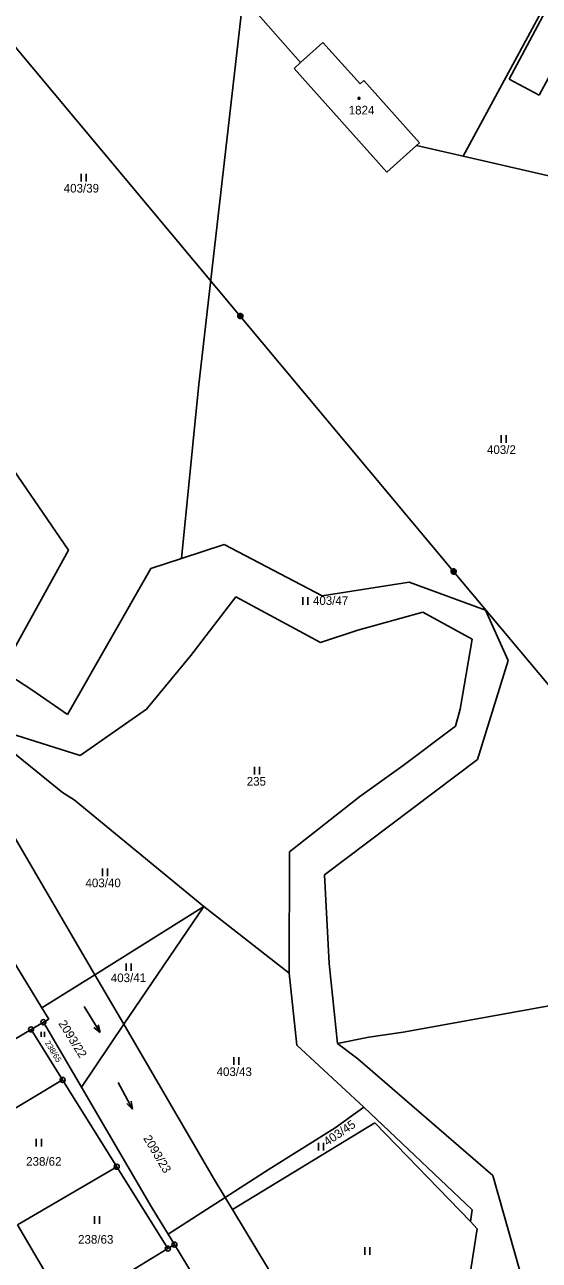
# Model space of a CAD drawing. Extents: x -795483 to -789093, y -1112258 to -1108741.
# Drawn here: x -791523.5 to -791422.1, y -1111209.4 to -1110965.8 of the extents above; entities that cross this region are included whole.
import ezdxf

# ---------------------------------------------------------------- set-up
doc = ezdxf.new("R2010")
doc.units = 0
for name, color, linetype in [('Vrstva 1', 7, 'Continuous'), ('Vrstva 12', 7, 'Continuous'), ('Vrstva 14', 7, 'Continuous'), ('Vrstva 15', 7, 'Continuous'), ('Vrstva 23', 7, 'Continuous'), ('Vrstva 25', 7, 'Continuous'), ('Vrstva 26', 7, 'Continuous'), ('Vrstva 28', 7, 'Continuous')]:
    doc.layers.add(name, color=color, linetype=linetype)

msp = doc.modelspace()

# ---------------------------------------------------------------- linework, layer by layer
at = {"layer": 'Vrstva 1'}
for p, q in [((-791417.2, -1110954.85), (-791437.16, -1110991.77)), ((-791428.08, -1110976.56), (-791416.64, -1110955.13)), ((-791410.64, -1110958.18), (-791422.14, -1110979.73)), ((-791480.51, -1110960.44), (-791489.29, -1111037.36)), ((-791480.51, -1110960.44), (-791469.18, -1110973.32)), ((-791464.78, -1110969.38), (-791469.18, -1110973.32)), ((-791464.78, -1110969.38), (-791457.46, -1110977.53)), ((-791470.46, -1110974.46), (-791469.18, -1110973.32)), ((-791470.46, -1110974.46), (-791452.15, -1110994.9)), ((-791457.46, -1110977.53), (-791456.71, -1110976.85)), ((-791456.71, -1110976.85), (-791445.73, -1110989.14)), ((-791422.14, -1110979.73), (-791428.08, -1110976.56)), ((-791445.73, -1110989.14), (-791446.31, -1110989.66)), ((-791452.15, -1110994.9), (-791446.31, -1110989.66)), ((-791446.31, -1110989.66), (-791437.16, -1110991.77)), ((-791437.16, -1110991.77), (-791391.97, -1111002.17)), ((-791566.04, -1110994.83), (-791514.9, -1111069.43)), ((-791489.29, -1111037.36), (-791492.66, -1111071.07)), ((-791514.9, -1111069.43), (-791528, -1111093.12)), ((-791484.25, -1111068.33), (-791492.66, -1111071.07)), ((-791484.25, -1111068.33), (-791464.93, -1111078.43)), ((-791498.67, -1111073.03), (-791492.66, -1111071.07)), ((-791515.12, -1111101.83), (-791498.67, -1111073.03)), ((-791464.93, -1111078.43), (-791447.81, -1111075.74)), ((-791447.81, -1111075.74), (-791432.71, -1111081.24)), ((-791481.94, -1111078.64), (-791490.78, -1111090.21)), ((-791481.94, -1111078.64), (-791465.25, -1111087.59)), ((-791457.92, -1111085.22), (-791445.08, -1111081.65)), ((-791445.08, -1111081.65), (-791435.37, -1111086.98)), ((-791432.71, -1111081.24), (-791428.25, -1111091.18)), ((-791465.25, -1111087.59), (-791457.92, -1111085.22)), ((-791437.72, -1111100.79), (-791435.37, -1111086.98)), ((-791499.56, -1111100.76), (-791490.78, -1111090.21)), ((-791428.25, -1111091.18), (-791434.3, -1111110.69)), ((-791528, -1111093.12), (-791522.13, -1111096.97)), ((-791522.13, -1111096.97), (-791515.12, -1111101.83)), ((-791512.58, -1111109.89), (-791499.56, -1111100.76)), ((-791438.63, -1111104.12), (-791437.72, -1111100.79)), ((-791533.06, -1111103.46), (-791512.58, -1111109.89)), ((-791533.06, -1111103.46), (-791516.11, -1111117.17)), ((-791448.93, -1111111.87), (-791438.63, -1111104.12)), ((-791552.06, -1111107.33), (-791520.15, -1111159.65)), ((-791536.7, -1111106.9), (-791509.72, -1111153.12)), ((-791434.3, -1111110.69), (-791464.44, -1111133.44)), ((-791457.52, -1111117.98), (-791448.93, -1111111.87)), ((-791516.11, -1111117.17), (-791513.78, -1111118.66)), ((-791471.33, -1111128.87), (-791457.52, -1111117.98)), ((-791488.21, -1111139.64), (-791513.78, -1111118.66)), ((-791471.33, -1111128.87), (-791471.4, -1111152.79)), ((-791464.44, -1111133.44), (-791463.52, -1111150.89)), ((-791509.72, -1111153.12), (-791488.21, -1111139.64)), ((-791488.21, -1111139.64), (-791504.02, -1111162.88)), ((-791488.21, -1111139.64), (-791471.4, -1111152.79)), ((-791463.52, -1111150.89), (-791461.89, -1111166.67)), ((-791520.15, -1111159.65), (-791509.72, -1111153.12)), ((-791509.72, -1111153.12), (-791504.02, -1111162.88)), ((-791471.4, -1111152.79), (-791469.91, -1111166.98)), ((-791448.95, -1111164.42), (-791401.41, -1111155.85)), ((-791520.15, -1111159.65), (-791518.81, -1111161.84)), ((-791518.81, -1111161.84), (-791519.85, -1111162.45)), ((-791541.09, -1111174.99), (-791522.29, -1111163.89)), ((-791522.29, -1111163.89), (-791519.85, -1111162.45)), ((-791516.08, -1111173.84), (-791522.29, -1111163.89)), ((-791513.94, -1111172.57), (-791519.85, -1111162.45)), ((-791504.02, -1111162.88), (-791512.35, -1111175.29)), ((-791486.32, -1111193.2), (-791504.02, -1111162.88)), ((-791455.73, -1111165.42), (-791448.95, -1111164.42)), ((-791456.74, -1111179.18), (-791469.91, -1111166.98)), ((-791461.89, -1111166.67), (-791455.73, -1111165.42)), ((-791461.89, -1111166.67), (-791457.92, -1111169.65)), ((-791457.92, -1111169.65), (-791431.26, -1111192.71)), ((-791535.12, -1111185.14), (-791516.08, -1111173.84)), ((-791505.4, -1111190.96), (-791516.08, -1111173.84)), ((-791513.94, -1111172.57), (-791512.35, -1111175.29)), ((-791512.35, -1111175.29), (-791498.42, -1111199.12)), ((-791456.74, -1111179.18), (-791462.36, -1111183.28)), ((-791435.39, -1111199.44), (-791456.74, -1111179.18)), ((-791482.6, -1111199.35), (-791454.56, -1111182.29)), ((-791462.36, -1111183.28), (-791475.38, -1111191.43)), ((-791454.56, -1111182.29), (-791435.71, -1111201.77)), ((-791524.94, -1111202.42), (-791505.4, -1111190.96)), ((-791505.4, -1111190.96), (-791495.34, -1111207.09)), ((-791486.32, -1111193.2), (-791484.03, -1111196.99)), ((-791475.38, -1111191.43), (-791484.03, -1111196.99)), ((-791422.96, -1111222.17), (-791431.26, -1111192.71)), ((-791484.03, -1111196.99), (-791495.3, -1111204.25)), ((-791484.03, -1111196.99), (-791482.6, -1111199.35)), ((-791495.3, -1111204.25), (-791498.42, -1111199.12)), ((-791482.6, -1111199.35), (-791460.81, -1111235.4)), ((-791435.39, -1111199.44), (-791435.71, -1111201.77)), ((-791524.94, -1111202.42), (-791515.11, -1111219.12)), ((-791434.35, -1111203.18), (-791436.4, -1111216.11)), ((-791435.71, -1111201.77), (-791434.35, -1111203.18)), ((-791494.05, -1111206.31), (-791495.3, -1111204.25)), ((-791495.34, -1111207.09), (-791515.11, -1111219.12)), ((-791495.34, -1111207.09), (-791494.05, -1111206.31)), ((-791483.17, -1111224.05), (-791494.05, -1111206.31))]:
    msp.add_line(p, q, dxfattribs=at)
at = {"layer": 'Vrstva 12'}
for p, q in [((-791526.73, -1110968.63), (-791481.05, -1111023.27)), ((-791481.05, -1111023.27), (-791439.03, -1111073.62)), ((-791439.03, -1111073.62), (-791390.3, -1111131.95))]:
    msp.add_line(p, q, dxfattribs=at)
at = {"layer": 'Vrstva 23'}
for p, q in [((-791512.44, -1110996.73), (-791512.44, -1110995.23)), ((-791511.44, -1110995.23), (-791511.44, -1110996.73)), ((-791429.65, -1111048.26), (-791429.65, -1111046.76)), ((-791428.65, -1111046.76), (-791428.65, -1111048.26)), ((-791468.74, -1111080.21), (-791468.74, -1111078.71)), ((-791467.74, -1111078.71), (-791467.74, -1111080.21)), ((-791478.28, -1111113.63), (-791478.28, -1111112.13)), ((-791477.28, -1111112.13), (-791477.28, -1111113.63)), ((-791508.2, -1111133.65), (-791508.2, -1111132.15)), ((-791507.2, -1111132.15), (-791507.2, -1111133.65)), ((-791503.55, -1111152.36), (-791503.55, -1111150.86)), ((-791502.55, -1111150.86), (-791502.55, -1111152.36)), ((-791511.84, -1111159.38), (-791508.7, -1111164.5)), ((-791520.29, -1111165.37), (-791520.29, -1111164.36)), ((-791519.61, -1111164.36), (-791519.61, -1111165.37)), ((-791508.7, -1111164.5), (-791509.91, -1111163.48)), ((-791508.7, -1111164.5), (-791509.06, -1111162.96)), ((-791482.32, -1111170.87), (-791482.32, -1111169.37)), ((-791481.32, -1111169.37), (-791481.32, -1111170.87)), ((-791505.15, -1111174.32), (-791502.27, -1111179.58)), ((-791502.27, -1111179.58), (-791503.43, -1111178.51)), ((-791502.27, -1111179.58), (-791502.55, -1111178.02)), ((-791521.26, -1111186.94), (-791521.26, -1111185.44)), ((-791520.26, -1111185.44), (-791520.26, -1111186.94)), ((-791465.66, -1111187.76), (-791465.66, -1111186.26)), ((-791464.66, -1111186.26), (-791464.66, -1111187.76)), ((-791509.77, -1111202.21), (-791509.77, -1111200.71)), ((-791508.77, -1111200.71), (-791508.77, -1111202.21)), ((-791456.52, -1111208.31), (-791456.52, -1111206.81)), ((-791455.52, -1111206.81), (-791455.52, -1111208.31))]:
    msp.add_line(p, q, dxfattribs=at)
at = {"layer": 'Vrstva 25'}
for p, q in [((-791457.81, -1110980.2), (-791457.51, -1110980.2)), ((-791457.81, -1110980.5), (-791457.81, -1110980.2)), ((-791457.51, -1110980.5), (-791457.81, -1110980.5)), ((-791457.51, -1110980.2), (-791457.51, -1110980.5))]:
    msp.add_line(p, q, dxfattribs=at)
at = {"layer": 'Vrstva 26'}
for p, q in [((-791481.55, -1111023.17), (-791481.45, -1111022.97)), ((-791481.55, -1111023.37), (-791481.55, -1111023.17)), ((-791481.45, -1111023.57), (-791481.55, -1111023.37)), ((-791481.45, -1111022.97), (-791481.35, -1111022.87)), ((-791481.35, -1111022.87), (-791481.15, -1111022.77)), ((-791481.35, -1111023.07), (-791481.35, -1111023.47)), ((-791481.15, -1111022.77), (-791480.95, -1111022.77)), ((-791481.15, -1111023.57), (-791481.15, -1111022.97)), ((-791481.15, -1111022.97), (-791480.95, -1111022.97)), ((-791480.95, -1111022.77), (-791480.75, -1111022.87)), ((-791480.95, -1111022.97), (-791480.95, -1111023.57)), ((-791480.75, -1111022.87), (-791480.65, -1111022.97)), ((-791480.75, -1111023.47), (-791480.75, -1111023.07)), ((-791480.65, -1111022.97), (-791480.55, -1111023.17)), ((-791480.55, -1111023.37), (-791480.65, -1111023.57)), ((-791480.55, -1111023.17), (-791480.55, -1111023.37)), ((-791481.35, -1111023.67), (-791481.45, -1111023.57)), ((-791481.35, -1111023.47), (-791481.15, -1111023.57)), ((-791481.15, -1111023.77), (-791481.35, -1111023.67)), ((-791480.95, -1111023.77), (-791481.15, -1111023.77)), ((-791480.95, -1111023.57), (-791480.75, -1111023.47)), ((-791480.75, -1111023.67), (-791480.95, -1111023.77)), ((-791480.65, -1111023.57), (-791480.75, -1111023.67)), ((-791439.53, -1111073.52), (-791439.43, -1111073.32)), ((-791439.53, -1111073.72), (-791439.53, -1111073.52)), ((-791439.43, -1111073.92), (-791439.53, -1111073.72)), ((-791439.43, -1111073.32), (-791439.33, -1111073.22)), ((-791439.33, -1111074.02), (-791439.43, -1111073.92)), ((-791439.33, -1111073.22), (-791439.13, -1111073.12)), ((-791439.33, -1111073.42), (-791439.33, -1111073.82)), ((-791439.33, -1111073.82), (-791439.13, -1111073.92)), ((-791439.13, -1111074.12), (-791439.33, -1111074.02)), ((-791439.13, -1111073.12), (-791438.93, -1111073.12)), ((-791439.13, -1111073.92), (-791439.13, -1111073.32)), ((-791439.13, -1111073.32), (-791438.93, -1111073.32)), ((-791438.93, -1111074.12), (-791439.13, -1111074.12)), ((-791438.93, -1111073.12), (-791438.73, -1111073.22)), ((-791438.93, -1111073.32), (-791438.93, -1111073.92)), ((-791438.93, -1111073.92), (-791438.73, -1111073.82)), ((-791438.73, -1111074.02), (-791438.93, -1111074.12)), ((-791438.73, -1111073.22), (-791438.63, -1111073.32)), ((-791438.73, -1111073.82), (-791438.73, -1111073.42)), ((-791438.63, -1111073.92), (-791438.73, -1111074.02)), ((-791438.63, -1111073.32), (-791438.53, -1111073.52)), ((-791438.53, -1111073.72), (-791438.63, -1111073.92)), ((-791438.53, -1111073.52), (-791438.53, -1111073.72))]:
    msp.add_line(p, q, dxfattribs=at)
at = {"layer": 'Vrstva 28'}
for centre, radius in [((-791519.85, -1111162.45), 0.5), ((-791522.29, -1111163.89), 0.5), ((-791522.29, -1111163.89), 0.01), ((-791519.85, -1111162.45), 0.01), ((-791516.08, -1111173.84), 0.5), ((-791516.08, -1111173.84), 0.01), ((-791505.4, -1111190.96), 0.5), ((-791505.4, -1111190.96), 0.01), ((-791494.05, -1111206.31), 0.5), ((-791495.34, -1111207.09), 0.5), ((-791495.34, -1111207.09), 0.01), ((-791494.05, -1111206.31), 0.01)]:
    msp.add_circle(centre, radius, dxfattribs=at)

# ---------------------------------------------------------------- texts
at = {"layer": 'Vrstva 14'}
for s, p in [('403/39', (-791515.85, -1110998.93)), ('403/2', (-791432.44, -1111050.46)), ('403/47', (-791466.74, -1111080.21)), ('235', (-791479.79, -1111115.83)), ('403/40', (-791511.56, -1111135.85)), ('403/43', (-791485.73, -1111173.07)), ('238/62', (-791523.25, -1111190.75)), ('238/63', (-791513.02, -1111206.12))]:
    msp.add_text(s, height=1.7, dxfattribs=at).set_placement(p)
for s, height, rotation, p in [('403/41', 1.7, 0.1931, (-791506.57, -1111154.57)), ('2093/22', 1.7, 301.8639, (-791516.97, -1111162.71)), ('238/65', 1.14, 301.3839, (-791519.61, -1111166.53)), ('403/45', 1.7, 34.133, (-791463.91, -1111186.91)), ('2093/23', 1.7, 300.6236, (-791500.23, -1111185.33))]:
    msp.add_text(s, height=height, rotation=rotation, dxfattribs=at).set_placement(p)
at = {"layer": 'Vrstva 15'}
msp.add_text('1824', height=1.7, dxfattribs=at).set_placement((-791459.69, -1110983.54))

doc.saveas('drawing.dxf')
